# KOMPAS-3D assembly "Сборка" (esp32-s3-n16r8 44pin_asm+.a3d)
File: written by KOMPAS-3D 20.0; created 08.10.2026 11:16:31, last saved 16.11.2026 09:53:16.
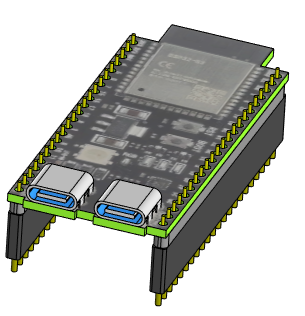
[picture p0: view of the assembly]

Document properties: Полное имя файла: D:\RicWork\Project-EPS32\box_compas\esp32\esp32-s3-n16r8 44pin_asm+.a3d

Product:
- Part/product: Сборка
    Масса: 0.0411431
  - Component [detail]: Деталь  | Масса: 0.019451; source file: esp32-s3-n16r8 44pin.m3d
  - Component [detail]: Деталь  | qty 2  | Масса: 0.00285166; source file: ..\разъемы\pls_22.m3d
  - Component [detail]: Деталь  | qty 2  | Масса: 0.00128034; source file: ..\разъемы\type-c female.m3d
  - Component [detail]: Деталь  | qty 2  | Масса: 0.00671403; source file: ..\разъемы\pbs_22.m3d

Referenced files in D:\RicWork\Project-EPS32\box_compas\разъемы\: pls_22.m3d, type-c female.m3d, pbs_22.m3d
Referenced files in D:\RicWork\Project-EPS32\box_compas\esp32\: esp32-s3-n16r8 44pin.m3d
